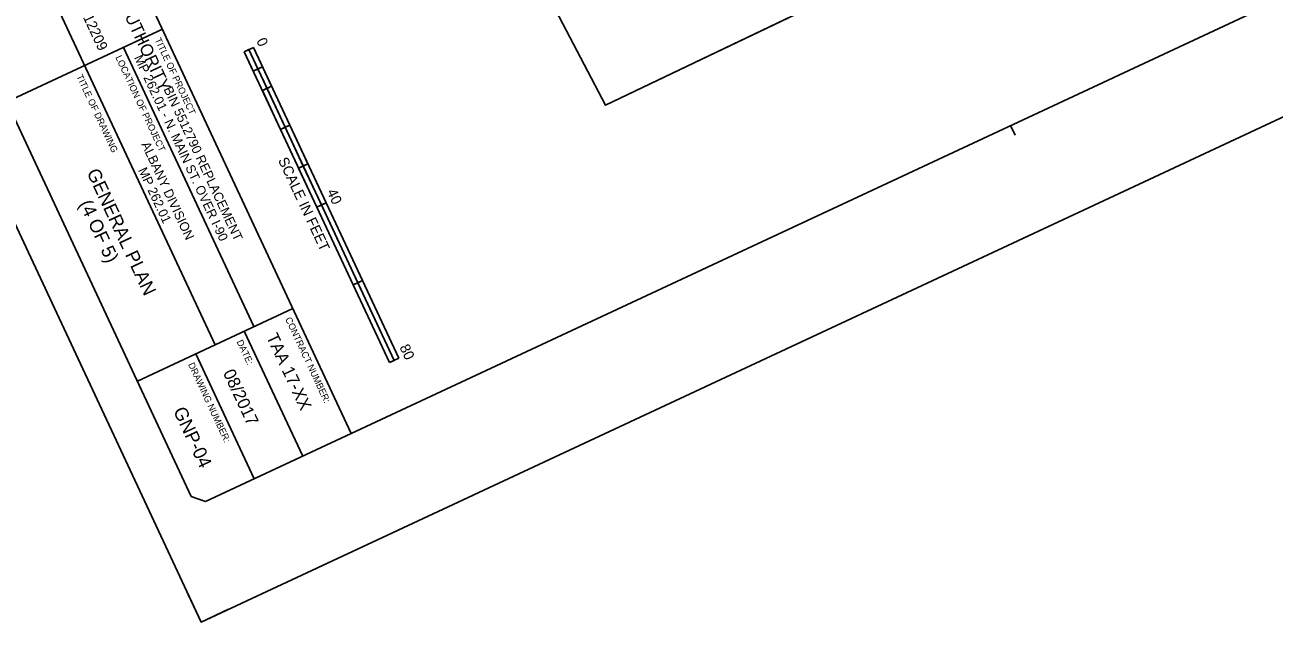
# Model space of a CAD drawing. Extents: x 1040814 to 1041501, y 1126274 to 1127077.
# Drawn here: x 1041061 to 1041352.2, y 1126274.4 to 1126413.6 of the extents above; entities that cross this region are included whole.
import ezdxf

# ---------------------------------------------------------------- set-up
doc = ezdxf.new("R2010")
doc.units = 0
for name, color, linetype in [('clip boundary', 7, 'Continuous'), ('NML_P', 7, 'Continuous'), ('NSB_P', 7, 'Continuous'), ('O_Details_Text Title and Subtitle Proposed_P_T', 7, 'Continuous'), ('SHEET_BORDER', 7, 'Continuous'), ('SHEET_BORDER_CUT', 7, 'Continuous'), ('SHEET_BORDER_TEXT', 7, 'Continuous')]:
    doc.layers.add(name, color=color, linetype=linetype)

msp = doc.modelspace()

# ---------------------------------------------------------------- linework, layer by layer
at = {"layer": 'clip boundary'}
for points in [[(1041212.91, 1127076.67), (1041500.71, 1126460.57), (1041102.06, 1126274.35), (1040814.26, 1126890.45)], [(1041214.88, 1127013.05), (1041436.47, 1126509.64), (1041196.3, 1126394.87), (1040940.57, 1126882.48)]]:
    msp.add_lwpolyline(points, close=True, dxfattribs=at)
at = {"layer": 'NML_P'}
msp.add_line((1041196.3, 1126394.87), (1041436.47, 1126509.64), dxfattribs=at)
at = {"layer": 'NSB_P'}
for p, q in [((1041112.1, 1126407.34), (1041114.27, 1126408.35)), ((1041113.18, 1126407.85), (1041112.1, 1126407.34)), ((1041113.18, 1126407.85), (1041147.04, 1126335.36)), ((1041115.3, 1126403.32), (1041113.18, 1126407.85)), ((1041114.27, 1126408.35), (1041148.13, 1126335.87)), ((1041112.1, 1126407.34), (1041145.96, 1126334.86)), ((1041112.1, 1126407.34), (1041114.21, 1126402.81)), ((1041114.21, 1126402.81), (1041116.39, 1126403.82)), ((1041114.21, 1126402.81), (1041115.3, 1126403.32)), ((1041116.39, 1126403.82), (1041115.3, 1126403.32)), ((1041115.3, 1126403.32), (1041117.42, 1126398.78)), ((1041118.5, 1126399.29), (1041116.39, 1126403.82)), ((1041116.33, 1126398.28), (1041118.5, 1126399.29)), ((1041117.42, 1126398.78), (1041118.5, 1126399.29)), ((1041117.42, 1126398.78), (1041116.33, 1126398.28)), ((1041116.33, 1126398.28), (1041120.56, 1126389.22)), ((1041121.65, 1126389.72), (1041117.42, 1126398.78)), ((1041120.56, 1126389.22), (1041122.74, 1126390.23)), ((1041122.74, 1126390.23), (1041121.65, 1126389.72)), ((1041126.97, 1126381.17), (1041122.74, 1126390.23)), ((1041120.56, 1126389.22), (1041121.65, 1126389.72)), ((1041121.65, 1126389.72), (1041125.88, 1126380.66)), ((1041124.79, 1126380.16), (1041126.97, 1126381.17)), ((1041125.88, 1126380.66), (1041124.79, 1126380.16)), ((1041124.79, 1126380.16), (1041129.03, 1126371.1)), ((1041125.88, 1126380.66), (1041126.97, 1126381.17)), ((1041130.11, 1126371.6), (1041125.88, 1126380.66)), ((1041129.03, 1126371.1), (1041131.2, 1126372.11)), ((1041129.03, 1126371.1), (1041130.11, 1126371.6)), ((1041131.2, 1126372.11), (1041130.11, 1126371.6)), ((1041130.11, 1126371.6), (1041138.58, 1126353.48)), ((1041139.67, 1126353.99), (1041131.2, 1126372.11)), ((1041137.49, 1126352.98), (1041139.67, 1126353.99)), ((1041138.58, 1126353.48), (1041137.49, 1126352.98)), ((1041137.49, 1126352.98), (1041145.96, 1126334.86)), ((1041138.58, 1126353.48), (1041139.67, 1126353.99)), ((1041147.04, 1126335.36), (1041138.58, 1126353.48)), ((1041145.96, 1126334.86), (1041148.13, 1126335.87)), ((1041145.96, 1126334.86), (1041147.04, 1126335.36))]:
    msp.add_line(p, q, dxfattribs=at)
at = {"layer": 'SHEET_BORDER'}
for p, q in [((1041137.06, 1126318.3), (1040994.93, 1126622.55)), ((1041105.32, 1126338.99), (1041044.48, 1126469.23)), ((1041093.02, 1126412.58), (1041056.78, 1126395.65)), ((1041114.38, 1126343.23), (1041083.96, 1126408.35)), ((1041290.8, 1126390.11), (1041291.86, 1126387.85)), ((1041087.2, 1126330.53), (1041123.44, 1126347.46)), ((1041125.73, 1126313.01), (1041112.11, 1126342.17)), ((1041114.41, 1126307.72), (1041100.79, 1126336.88))]:
    msp.add_line(p, q, dxfattribs=at)
msp.add_lwpolyline([(1041103.08, 1126302.42), (1041099.76, 1126303.63), (1040835.24, 1126869.9), (1040836.45, 1126873.22), (1041211.88, 1127048.6), (1041215.2, 1127047.39), (1041479.72, 1126481.12), (1041478.52, 1126477.8)], close=True, dxfattribs=at)
at = {"layer": 'SHEET_BORDER_CUT'}
msp.add_lwpolyline([(1040814.26, 1126890.45), (1041102.06, 1126274.35), (1041500.71, 1126460.57), (1041212.91, 1127076.67)], close=True, dxfattribs=at)
msp.add_lwpolyline([(1041108.46, 1126277.34), (1041102.06, 1126274.35), (1041099.06, 1126280.76)], dxfattribs=at)
at = {"layer": 'SHEET_BORDER_TEXT'}
msp.add_line((1041102.06, 1126274.35), (1041102.06, 1126274.35), dxfattribs=at)

# ---------------------------------------------------------------- texts
at = {"layer": 'NSB_P'}
for s, p in [('0', (1041114.87, 1126409.9)), ('SCALE IN FEET', (1041119.94, 1126382.05)), ('40', (1041131.32, 1126374.69)), ('80', (1041148.25, 1126338.45))]:
    msp.add_text(s, height=2.4, rotation=295.0387, dxfattribs=at).set_placement(p)
at = {"layer": 'O_Details_Text Title and Subtitle Proposed_P_T'}
for s, height, p in [('GENERAL PLAN', 3.1248, (1041075.31, 1126379.2)), ('(4 OF 5)', 3.125, (1041073.55, 1126371.9)), ('GNP-04', 3.125, (1041095.48, 1126323.63))]:
    msp.add_text(s, height=height, rotation=295.0387, dxfattribs=at).set_placement(p)
at = {"layer": 'SHEET_BORDER'}
for s, height, p in [('NEW YORK STATE THRUWAY AUTHORITY', 2.88, (1041059.35, 1126468.74)), ('200 SOUTHERN BLVD., ALBANY, N.Y. 12209', 2.4, (1041050, 1126467.76)), ('TITLE OF PROJECT', 1.5625, (1041091.19, 1126410.13)), ('LOCATION OF PROJECT', 1.5625, (1041082.02, 1126406.04)), ('TITLE OF DRAWING', 1.5625, (1041072.92, 1126401.6)), ('CONTRACT NUMBER:', 1.5625, (1041121.61, 1126345.01)), ('DATE:', 1.562, (1041110.28, 1126339.72)), ('DRAWING NUMBER:', 1.5625, (1041098.96, 1126334.43))]:
    msp.add_text(s, height=height, rotation=295.0387, dxfattribs=at).set_placement(p)
at = {"layer": 'SHEET_BORDER_TEXT'}
for s, height, p in [('MP 262.01 - N. MAIN ST. OVER I-90', 2.16, (1041086.37, 1126405.97)), ('BIN 5512790 REPLACEMENT', 2.16, (1041093.24, 1126398.62)), ('ALBANY DIVISION', 2.16, (1041088.04, 1126385.75)), ('MP 262.01', 2.16, (1041087.33, 1126379.74)), ('TAA 17-XX', 2.88, (1041117.16, 1126340.88)), ('08/2017', 2.88, (1041107.09, 1126332.47))]:
    msp.add_text(s, height=height, rotation=295.0387, dxfattribs=at).set_placement(p)

doc.saveas('drawing.dxf')
